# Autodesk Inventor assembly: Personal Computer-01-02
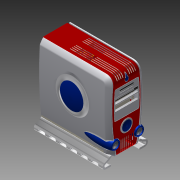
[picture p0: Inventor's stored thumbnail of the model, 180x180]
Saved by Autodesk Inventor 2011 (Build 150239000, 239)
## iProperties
Company: Autodesk Inc.
Created: 2008-02
Part Number: Personal Computer-01-02
Document SubType Name: Assembly
Designer: hendert
Mass: 4524.54 g
Surface Area: 24845.8 cm^2
Volume: 4524.54 cm^3
Density: 1 g/cm^3
Title: Personal Computer
Author: hendert
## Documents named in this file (15)
- C:\Users\Public\Documents\Autodesk\Inventor 2011\Samples\Models\Assemblies\Personal Computer\Personal Computer\ALIAS Conceptual PC Case.iam
- C:\Users\Public\Documents\Autodesk\Inventor 2011\Samples\Models\Assemblies\Personal Computer\PC Chassis\PC Chassis.iam
- C:\Users\Public\Documents\Autodesk\Inventor 2011\Samples\Models\Assemblies\Personal Computer\Motherboard\Motherboard.iam
- C:\Users\Public\Documents\Autodesk\Inventor 2011\Samples\Models\Assemblies\Personal Computer\Graphics Card\Graphics Card.iam
- C:\Users\Public\Documents\Autodesk\Inventor 2011\Samples\Models\Assemblies\Personal Computer\Power Supply\Power Supply.iam
- C:\Users\Public\Documents\Autodesk\Inventor 2011\Samples\Models\Assemblies\Personal Computer\Drives\CDROM.ipt
- C:\Users\Public\Documents\Autodesk\Inventor 2011\Samples\Models\Assemblies\Personal Computer\Drives\Hard Drive.ipt
- C:\Users\Public\Documents\Autodesk\Inventor 2011\Samples\Models\Assemblies\Personal Computer\Aip\CD Ribbon Cable.iam
- C:\Users\Public\Documents\Autodesk\Inventor 2011\Samples\Models\Assemblies\Personal Computer\PC Cover\Alias Conceptual PC Cover\Alias Conceptual PC Cover.ipt
- C:\Users\Public\Documents\Autodesk\Inventor 2011\Samples\Models\Assemblies\Personal Computer\Aip\Power Supply Harness.iam
- C:\Users\Public\Documents\Autodesk\Inventor 2011\Samples\Models\Assemblies\Personal Computer\Aip\Cooling Fan Harness.iam
- C:\Users\Public\Documents\Autodesk\Inventor 2011\Samples\Models\Assemblies\Personal Computer\Aip\Processor Fan Harness.iam
- C:\Users\Public\Documents\Autodesk\Inventor 2011\Samples\Models\Assemblies\Personal Computer\Aip\Front Panel Harness.iam
- C:\Users\Public\Documents\Autodesk\Inventor 2011\Samples\Models\Assemblies\Personal Computer\Aip\HD Ribbon Cable.iam
- C:\Users\Public\Documents\Autodesk\Inventor 2011\Samples\Models\Assemblies\Personal Computer\Personal Computer.iam
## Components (15 placed, 13 different names)
1. PC Chassis:1 [sub-assembly] — Mate:1, Mate:3, Mate:7, Mate:8, Mate:9, Mate:10, Mate:11, Angle:1, Mate:12, Mate:13, Angle:2, Mate:14, Mate:15, Angle:3, Mate:16, Mate:17, Angle:4
2. Alias Conceptual PC Cover:1 — Flush:7, Flush:8
3. Power Supply:1 [sub-assembly] — Mate:7, Mate:8, Mate:9, Mate:87, Mate:88, Mate:89, Mate:90, Mate:91, Mate:92, Mate:93, Mate:94, Mate:95, Mate:96, Mate:97, Mate:98, Mate:99, Mate:100, Mate:101, Mate:102, Mate:103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
4. Motherboard:1 [sub-assembly] — Mate:5, Mate:6, Mate:32, Mate:33, Mate:34, Mate:107, Flush:10, Flush:11, Mate:108, Flush:12, Flush:13, Mate:121, Mate:122, Mate:123, Mate:124, Mate:125, Mate:126, Mate:127, Mate:128, Mate:129
5. Graphics Card:1 [sub-assembly] — Mate:1, Mate:3, Mate:5, Mate:6
6. CDROM:1 — Mate:10, Mate:11, Angle:1, Mate:44, Mate:45, Mate:46, Mate:109, Mate:110, Mate:111
7. CDROM:2 — Mate:12, Mate:13, Angle:2, Mate:38, Mate:39, Mate:40, Mate:112, Mate:113, Mate:114
8. Hard Drive:1 — Mate:16, Mate:17, Angle:4, Mate:115, Mate:116, Mate:117, Mate:133, Mate:134, Mate:135
9. Hard Drive:2 — Mate:14, Mate:15, Angle:3, Mate:118, Mate:119, Mate:120, Mate:130, Mate:131, Mate:132
10. CD Ribbon Cable [sub-assembly] — Mate:32, Mate:33, Mate:34, Mate:38, Mate:39, Mate:40, Mate:44, Mate:45, Mate:46
11. Power Supply Harness [sub-assembly] — Mate:87, Mate:88, Mate:89, Mate:90, Mate:91, Mate:92, Mate:93, Mate:94, Mate:95, Mate:96, Mate:97, Mate:98, Mate:99, Mate:100, Mate:101, Mate:102, Mate:103, Mate:104, Mate:105, Mate:106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
12. Cooling Fan Harness [sub-assembly]
13. Processor Fan Harness [sub-assembly] — Mate:121, Mate:122, Mate:123
14. Front Panel Harness [sub-assembly] — Mate:124, Mate:125, Mate:126
15. HD Ribbon Cable [sub-assembly] — Mate:127, Mate:128, Mate:129, Mate:130, Mate:131, Mate:132, Mate:133, Mate:134, Mate:135
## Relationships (83: Mate 73, Flush 6, Angle 4)
- Mate:1: PC Chassis:1 ↔ Graphics Card:1
- Mate:3: PC Chassis:1 ↔ Graphics Card:1
- Mate:5: Motherboard:1 ↔ Graphics Card:1
- Mate:6: Motherboard:1 ↔ Graphics Card:1
- Mate:7: PC Chassis:1 ↔ Power Supply:1
- Mate:8: PC Chassis:1 ↔ Power Supply:1
- Mate:9: PC Chassis:1 ↔ Power Supply:1
- Mate:10: PC Chassis:1 ↔ CDROM:1
- Mate:11: PC Chassis:1 ↔ CDROM:1
- Angle:1: PC Chassis:1 ↔ CDROM:1
- Mate:12: PC Chassis:1 ↔ CDROM:2
- Mate:13: PC Chassis:1 ↔ CDROM:2
- Angle:2: PC Chassis:1 ↔ CDROM:2
- Mate:14: PC Chassis:1 ↔ Hard Drive:2
- Mate:15: PC Chassis:1 ↔ Hard Drive:2
- Angle:3: PC Chassis:1 ↔ Hard Drive:2
- Mate:16: PC Chassis:1 ↔ Hard Drive:1
- Mate:17: PC Chassis:1 ↔ Hard Drive:1
- Angle:4: PC Chassis:1 ↔ Hard Drive:1
- Mate:32: Motherboard:1 ↔ CD Ribbon Cable
- Mate:33: Motherboard:1 ↔ CD Ribbon Cable
- Mate:34: Motherboard:1 ↔ CD Ribbon Cable
- Mate:38: CDROM:2 ↔ CD Ribbon Cable
- Mate:39: CDROM:2 ↔ CD Ribbon Cable
- Mate:40: CDROM:2 ↔ CD Ribbon Cable
- Mate:44: CDROM:1 ↔ CD Ribbon Cable
- Mate:45: CDROM:1 ↔ CD Ribbon Cable
- Mate:46: CDROM:1 ↔ CD Ribbon Cable
- Flush:7: Alias Conceptual PC Cover:1
- Flush:8: Alias Conceptual PC Cover:1
- Mate:87: Power Supply:1 ↔ Power Supply Harness
- Mate:88: Power Supply:1 ↔ Power Supply Harness
- Mate:89: Power Supply:1 ↔ Power Supply Harness
- Mate:90: Power Supply:1 ↔ Power Supply Harness
- Mate:91: Power Supply:1 ↔ Power Supply Harness
- Mate:92: Power Supply:1 ↔ Power Supply Harness
- Mate:93: Power Supply:1 ↔ Power Supply Harness
- Mate:94: Power Supply:1 ↔ Power Supply Harness
- Mate:95: Power Supply:1 ↔ Power Supply Harness
- Mate:96: Power Supply:1 ↔ Power Supply Harness
- Mate:97: Power Supply:1 ↔ Power Supply Harness
- Mate:98: Power Supply:1 ↔ Power Supply Harness
- Mate:99: Power Supply:1 ↔ Power Supply Harness
- Mate:100: Power Supply:1 ↔ Power Supply Harness
- Mate:101: Power Supply:1 ↔ Power Supply Harness
- Mate:102: Power Supply:1 ↔ Power Supply Harness
- Mate:103: Power Supply:1 ↔ Power Supply Harness
- Mate:104: Power Supply:1 ↔ Power Supply Harness
- Mate:105: Power Supply:1 ↔ Power Supply Harness
- Mate:106: Power Supply:1 ↔ Power Supply Harness
- Mate:107: Motherboard:1 ↔ Power Supply Harness
- Flush:10: Motherboard:1 ↔ Power Supply Harness
- Flush:11: Motherboard:1 ↔ Power Supply Harness
- Mate:108: Motherboard:1 ↔ Power Supply Harness
- Flush:12: Motherboard:1 ↔ Power Supply Harness
- Flush:13: Motherboard:1 ↔ Power Supply Harness
- Mate:109: CDROM:1 ↔ Power Supply Harness
- Mate:110: CDROM:1 ↔ Power Supply Harness
- Mate:111: CDROM:1 ↔ Power Supply Harness
- Mate:112: CDROM:2 ↔ Power Supply Harness
- Mate:113: CDROM:2 ↔ Power Supply Harness
- Mate:114: CDROM:2 ↔ Power Supply Harness
- Mate:115: Hard Drive:1 ↔ Power Supply Harness
- Mate:116: Hard Drive:1 ↔ Power Supply Harness
- Mate:117: Hard Drive:1 ↔ Power Supply Harness
- Mate:118: Hard Drive:2 ↔ Power Supply Harness
- Mate:119: Hard Drive:2 ↔ Power Supply Harness
- Mate:120: Hard Drive:2 ↔ Power Supply Harness
- Mate:121: Motherboard:1 ↔ Processor Fan Harness
- Mate:122: Motherboard:1 ↔ Processor Fan Harness
- Mate:123: Motherboard:1 ↔ Processor Fan Harness
- Mate:124: Motherboard:1 ↔ Front Panel Harness
- Mate:125: Motherboard:1 ↔ Front Panel Harness
- Mate:126: Motherboard:1 ↔ Front Panel Harness
- Mate:127: Motherboard:1 ↔ HD Ribbon Cable
- Mate:128: Motherboard:1 ↔ HD Ribbon Cable
- Mate:129: Motherboard:1 ↔ HD Ribbon Cable
- Mate:130: Hard Drive:2 ↔ HD Ribbon Cable
- Mate:131: Hard Drive:2 ↔ HD Ribbon Cable
- Mate:132: Hard Drive:2 ↔ HD Ribbon Cable
- Mate:133: Hard Drive:1 ↔ HD Ribbon Cable
- Mate:134: Hard Drive:1 ↔ HD Ribbon Cable
- Mate:135: Hard Drive:1 ↔ HD Ribbon Cable
